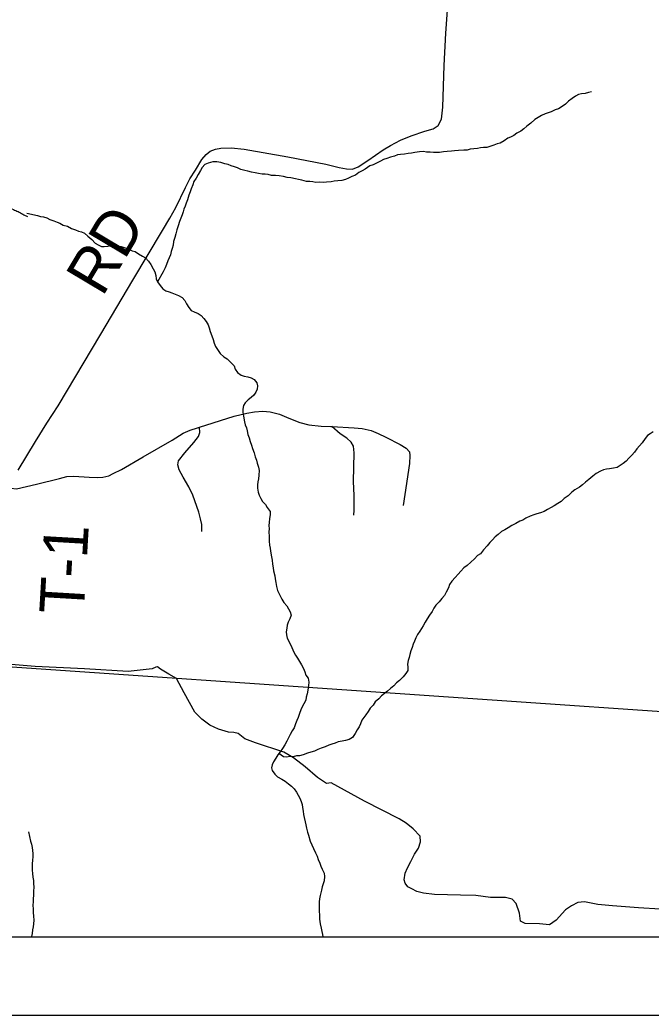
# Model space of a CAD drawing. Extents: x -8.2 to 34, y 0 to 22.
# Drawn here: x 7.291 to 8.096, y 14 to 15.27 of the extents above; entities that cross this region are included whole.
import ezdxf

# ---------------------------------------------------------------- set-up
doc = ezdxf.new("R2010")
doc.units = 0
for name, color, linetype in [('GM_X_Corporation', 7, 'Continuous'), ('GM_X_Minor_River', 7, 'Continuous'), ('GM_X_Township_Road', 7, 'Continuous'), ('GM_X_Township_Road_Text', 7, 'Continuous'), ('SH_Data', 7, 'Continuous')]:
    doc.layers.add(name, color=color, linetype=linetype)

msp = doc.modelspace()

# ---------------------------------------------------------------- linework, layer by layer
at = {"layer": 'GM_X_Corporation'}
for points in [[(4.1481, 14.1), (8.9, 14.1), (8.9, 15.3663), (8.5054, 15.392), (7.8479, 15.4343), (7.082, 15.4841), (6.7558, 15.5053), (6.7389, 15.5064), (6.2987, 15.5287), (5.4088, 15.5882), (4.4836, 15.6492), (4.4152, 15.6505), (4.2922, 15.6569), (4.2674, 15.658), (4.2558, 15.6585), (4.2352, 15.4906), (4.2113, 15.0848), (4.1846, 14.6878), (4.1741, 14.5315), (4.1604, 14.3288)], [(7.2372, 14.1), (8.2568, 14.1), (8.2775, 14.3753), (7.2616, 14.4454)]]:
    msp.add_lwpolyline(points, close=True, dxfattribs=at)
at = {"layer": 'GM_X_Minor_River'}
for points in [[(8.0203, 15.1781), (8.0165, 15.177), (8.0123, 15.1758), (8.0078, 15.1755), (8.004, 15.1747), (7.9998, 15.1724), (7.9956, 15.1694), (7.9911, 15.1659), (7.9873, 15.1621), (7.9831, 15.1595), (7.9782, 15.1564), (7.974, 15.1549), (7.9687, 15.1526), (7.9649, 15.1511), (7.9611, 15.1499), (7.9566, 15.148), (7.9524, 15.1453), (7.9482, 15.1427), (7.9429, 15.1381), (7.938, 15.1343), (7.9338, 15.1309), (7.93, 15.1278), (7.9251, 15.1252), (7.9213, 15.1225), (7.9171, 15.1202), (7.9134, 15.1187), (7.9088, 15.1156), (7.9039, 15.1126), (7.9001, 15.1115), (7.8959, 15.1099), (7.8917, 15.1088), (7.8868, 15.1072), (7.8826, 15.1069), (7.8788, 15.1065), (7.875, 15.1057), (7.8701, 15.1053), (7.8655, 15.1049), (7.8617, 15.1038), (7.8572, 15.1038), (7.8504, 15.103), (7.8454, 15.1026), (7.8416, 15.1022), (7.8363, 15.1018), (7.8314, 15.1014), (7.8264, 15.1006), (7.8223, 15.1006), (7.8185, 15.1006), (7.8143, 15.101), (7.8097, 15.101), (7.8059, 15.1017), (7.8006, 15.1013), (7.7949, 15.1006), (7.7907, 15.0998), (7.7862, 15.0994), (7.7816, 15.0986), (7.7767, 15.0982), (7.7729, 15.0975), (7.7687, 15.0959), (7.7638, 15.0948), (7.7589, 15.0929), (7.7547, 15.0917), (7.7509, 15.0895), (7.7467, 15.0875), (7.7418, 15.0849), (7.7376, 15.0834), (7.7316, 15.0795), (7.7274, 15.0773), (7.7232, 15.075), (7.7191, 15.0719), (7.7145, 15.07), (7.7103, 15.0677), (7.7062, 15.0662), (7.7016, 15.0647), (7.6967, 15.0643), (7.6917, 15.0639), (7.6879, 15.0631), (7.6822, 15.0627), (7.6777, 15.0623), (7.6731, 15.0627), (7.6686, 15.0623), (7.6648, 15.0631), (7.6606, 15.0634), (7.6564, 15.0638), (7.6507, 15.0653), (7.6462, 15.0661), (7.6424, 15.0672), (7.6367, 15.0683), (7.6317, 15.0687), (7.6272, 15.0698), (7.6215, 15.0709), (7.6169, 15.0713), (7.612, 15.0713), (7.6074, 15.0724), (7.6036, 15.0728), (7.5998, 15.0728), (7.5953, 15.0739), (7.5911, 15.0746), (7.5865, 15.0754), (7.5816, 15.0769), (7.5778, 15.0776), (7.5725, 15.0791)], [(7.5725, 15.0791), (7.5683, 15.081), (7.5645, 15.0825), (7.5603, 15.0837), (7.5565, 15.0852), (7.5523, 15.0863), (7.547, 15.0878), (7.5421, 15.0886), (7.5371, 15.0885), (7.531, 15.087), (7.5269, 15.0851), (7.5235, 15.0813), (7.5212, 15.0775), (7.5182, 15.0726), (7.5155, 15.068), (7.5125, 15.0634), (7.5114, 15.0593), (7.5095, 15.0543), (7.508, 15.0505), (7.5065, 15.046), (7.5046, 15.0403), (7.5031, 15.0361), (7.5016, 15.0323), (7.5001, 15.0285), (7.4989, 15.0247), (7.4978, 15.0209), (7.4959, 15.0167), (7.4944, 15.0126), (7.4925, 15.0069), (7.491, 15.0019), (7.4895, 14.997), (7.4884, 14.9921), (7.4869, 14.9871), (7.4861, 14.9822), (7.485, 14.978), (7.4839, 14.9742), (7.4827, 14.9701), (7.4812, 14.9663), (7.4797, 14.9625), (7.4778, 14.9579), (7.4763, 14.9533), (7.4737, 14.9484), (7.4662, 14.9354)], [(7.2994, 15.0231), (7.3129, 15.0201), (7.3171, 15.019), (7.3209, 15.0186), (7.325, 15.0171), (7.3288, 15.0152), (7.3338, 15.0133), (7.338, 15.0118), (7.3418, 15.0103), (7.3459, 15.008), (7.3513, 15.0065), (7.3566, 15.0035), (7.3615, 15.002), (7.3653, 15.0001), (7.3691, 14.9994), (7.3733, 14.9975), (7.3775, 14.9937), (7.3824, 14.9895), (7.3866, 14.985), (7.3904, 14.9827), (7.3946, 14.9805), (7.3984, 14.9805), (7.403, 14.9809), (7.4072, 14.982), (7.4109, 14.982), (7.4155, 14.9816), (7.4201, 14.9805), (7.425, 14.979), (7.4292, 14.9771), (7.4338, 14.9752), (7.4379, 14.9741), (7.4421, 14.9715), (7.4471, 14.9684), (7.4509, 14.9662), (7.4547, 14.962), (7.4577, 14.9575), (7.4608, 14.9522), (7.4631, 14.9484), (7.4642, 14.9438), (7.4646, 14.9393), (7.4661, 14.9355), (7.4696, 14.931), (7.473, 14.9268), (7.4768, 14.9241), (7.481, 14.923), (7.4848, 14.9215), (7.489, 14.92), (7.4931, 14.9181), (7.4977, 14.9155), (7.5011, 14.9117), (7.5034, 14.9075), (7.5061, 14.903), (7.5091, 14.8992), (7.5133, 14.8973), (7.5183, 14.895), (7.5221, 14.8928), (7.5255, 14.889), (7.5285, 14.8848), (7.5308, 14.8807), (7.5324, 14.8769), (7.5335, 14.8723), (7.5358, 14.8666), (7.5373, 14.8621), (7.5385, 14.8575), (7.5404, 14.853), (7.5438, 14.8481), (7.5461, 14.8443), (7.5511, 14.8401), (7.5552, 14.8375), (7.5598, 14.8326), (7.564, 14.8284), (7.5655, 14.8242), (7.5686, 14.8201), (7.5732, 14.8167), (7.577, 14.8152), (7.5815, 14.8144), (7.5861, 14.8129), (7.5899, 14.811), (7.5933, 14.8069), (7.5941, 14.8031), (7.5937, 14.7985), (7.5918, 14.7947), (7.5895, 14.7909), (7.5858, 14.7882), (7.582, 14.7852), (7.5782, 14.7814), (7.5763, 14.7776), (7.5752, 14.7731), (7.5752, 14.7693), (7.5759, 14.7643), (7.5775, 14.7571), (7.5783, 14.7533), (7.5798, 14.7492), (7.5806, 14.7454), (7.5817, 14.7408), (7.5832, 14.7367), (7.5848, 14.7317), (7.5863, 14.7272), (7.5878, 14.723), (7.5897, 14.7173), (7.5909, 14.7124)], [(8.0993, 14.744), (8.0955, 14.7417), (8.0917, 14.7395), (8.0887, 14.7357), (8.0849, 14.7303), (8.0815, 14.7265), (8.0784, 14.7227), (8.0754, 14.7182), (8.072, 14.7144), (8.0682, 14.7106), (8.0648, 14.7068), (8.061, 14.7037), (8.0572, 14.7011), (8.0531, 14.6988), (8.0485, 14.698), (8.0432, 14.6969), (8.0394, 14.6965), (8.0356, 14.6957), (8.0318, 14.6942), (8.0265, 14.6911), (8.022, 14.6877), (8.017, 14.6835), (8.0129, 14.6801), (8.0087, 14.6767), (8.0049, 14.6736), (7.9992, 14.6702), (7.9954, 14.6671), (7.9905, 14.6626), (7.9856, 14.6592), (7.9818, 14.6554)], [(7.5909, 14.7124), (7.5928, 14.7082), (7.5936, 14.7044), (7.5951, 14.6991), (7.5959, 14.695), (7.5955, 14.6889), (7.5951, 14.6844), (7.5944, 14.6806), (7.594, 14.6764), (7.594, 14.6722), (7.5948, 14.6673), (7.596, 14.6635), (7.5982, 14.6593), (7.6002, 14.6555), (7.604, 14.6514), (7.6063, 14.6476), (7.6101, 14.6427), (7.6101, 14.6381), (7.6093, 14.6336), (7.609, 14.6286), (7.6086, 14.6248), (7.609, 14.6203), (7.6086, 14.6165), (7.609, 14.6108), (7.609, 14.6047), (7.6094, 14.5998), (7.6102, 14.5956), (7.6106, 14.5918), (7.6117, 14.5846), (7.6125, 14.5805), (7.6133, 14.5755), (7.614, 14.5706), (7.6144, 14.5668), (7.616, 14.5604), (7.6167, 14.5566), (7.6175, 14.552), (7.6183, 14.5467), (7.6194, 14.5418), (7.6221, 14.5365), (7.6252, 14.5308), (7.6278, 14.5263), (7.6313, 14.5221), (7.6336, 14.5183), (7.6355, 14.5145), (7.637, 14.5104), (7.6351, 14.5058), (7.6332, 14.5013), (7.6317, 14.4975), (7.6313, 14.4937), (7.6306, 14.4891), (7.631, 14.4853), (7.6318, 14.4808), (7.6348, 14.4755), (7.6379, 14.469), (7.6405, 14.463), (7.6424, 14.4592), (7.6451, 14.4554), (7.6474, 14.4512), (7.6501, 14.4467), (7.6527, 14.4421), (7.6543, 14.438), (7.6558, 14.4338), (7.6585, 14.43), (7.6596, 14.4247), (7.6589, 14.4205), (7.6581, 14.4145), (7.6574, 14.4099), (7.6563, 14.4057), (7.6555, 14.4019), (7.6532, 14.397), (7.651, 14.3932), (7.6495, 14.3894), (7.6476, 14.3849), (7.6457, 14.3799), (7.6442, 14.3757), (7.6427, 14.3716), (7.6408, 14.3666), (7.6381, 14.3625), (7.6355, 14.3579), (7.6336, 14.3537), (7.6313, 14.3495), (7.6287, 14.345), (7.626, 14.3401), (7.623, 14.3359), (7.62, 14.3321), (7.6173, 14.3279), (7.6143, 14.3233), (7.6128, 14.3195), (7.6117, 14.3157), (7.6125, 14.3119), (7.6159, 14.3074), (7.6197, 14.304), (7.625, 14.301), (7.6292, 14.2983), (7.6334, 14.2949), (7.6372, 14.2923), (7.641, 14.2885), (7.6437, 14.2843), (7.6459, 14.2806), (7.6479, 14.2768), (7.6498, 14.2726)], [(7.9818, 14.6554), (7.9776, 14.6527), (7.9727, 14.6496), (7.9689, 14.6477), (7.9643, 14.6451), (7.9598, 14.6424), (7.9552, 14.6409), (7.9507, 14.6397), (7.9469, 14.6382), (7.9423, 14.6367), (7.9367, 14.634), (7.9329, 14.6317), (7.9287, 14.6302), (7.9238, 14.6271), (7.9185, 14.6245), (7.9139, 14.6218), (7.9097, 14.6191), (7.9056, 14.6169), (7.9014, 14.6131), (7.8976, 14.6104), (7.8942, 14.6066), (7.8908, 14.6028), (7.887, 14.5986), (7.8825, 14.5937), (7.8787, 14.5887), (7.8749, 14.5864), (7.8711, 14.5823), (7.8662, 14.5781), (7.8616, 14.5735), (7.8575, 14.5705), (7.8537, 14.5663), (7.8503, 14.5625), (7.8465, 14.5583), (7.8419, 14.5537), (7.8393, 14.5496), (7.8378, 14.545), (7.8348, 14.5397), (7.8329, 14.5355), (7.8295, 14.5317), (7.8257, 14.5271), (7.8215, 14.523), (7.8189, 14.5192), (7.817, 14.515), (7.8136, 14.5101), (7.8105, 14.5055), (7.8079, 14.5013), (7.8056, 14.4968), (7.8011, 14.4899), (7.7984, 14.4857), (7.7962, 14.4812), (7.7943, 14.477), (7.7928, 14.4732), (7.7913, 14.469), (7.7898, 14.4649), (7.7886, 14.4603), (7.7875, 14.4561), (7.7864, 14.4523), (7.7856, 14.4478), (7.786, 14.444), (7.7857, 14.4398), (7.7834, 14.436), (7.78, 14.4318), (7.7754, 14.4269), (7.7713, 14.4239), (7.7679, 14.4201), (7.7637, 14.4166), (7.7599, 14.4132), (7.7561, 14.4105), (7.7523, 14.4075), (7.7489, 14.4037), (7.7444, 14.3999), (7.7417, 14.3953), (7.7379, 14.3915), (7.7353, 14.3874), (7.7323, 14.3832), (7.7273, 14.3763), (7.7255, 14.3718), (7.7236, 14.368), (7.7213, 14.3638), (7.7187, 14.3592), (7.7152, 14.3543), (7.7111, 14.3516), (7.7065, 14.3505), (7.702, 14.3497), (7.697, 14.3486), (7.6932, 14.347), (7.6887, 14.3455), (7.6849, 14.3444), (7.6803, 14.3421), (7.6754, 14.3406), (7.6709, 14.339), (7.6667, 14.3367), (7.6621, 14.3356), (7.6576, 14.3341), (7.6523, 14.3322), (7.6477, 14.331), (7.6439, 14.3306), (7.6394, 14.3295), (7.6356, 14.3298), (7.631, 14.3291), (7.6272, 14.3294)], [(7.6272, 14.3294), (7.6212, 14.3336)], [(7.6498, 14.2726), (7.6509, 14.2688), (7.6513, 14.265), (7.6521, 14.2601), (7.6528, 14.2559), (7.6536, 14.2521), (7.6548, 14.2468), (7.6555, 14.2427), (7.6567, 14.2385), (7.6578, 14.2336), (7.659, 14.2294), (7.6613, 14.2218), (7.6632, 14.2173), (7.6655, 14.2127), (7.6682, 14.207), (7.6701, 14.2029), (7.6716, 14.1987), (7.6735, 14.1938), (7.675, 14.19), (7.6766, 14.1862), (7.6789, 14.1809), (7.6796, 14.1767), (7.6789, 14.1714), (7.6778, 14.1676), (7.6766, 14.1638), (7.6755, 14.1593), (7.674, 14.1524), (7.6733, 14.1483), (7.6729, 14.1445), (7.6729, 14.1403), (7.6729, 14.1361), (7.6729, 14.1323), (7.6733, 14.1278), (7.6733, 14.1225), (7.6741, 14.1164), (7.6753, 14.1111), (7.676, 14.1065), (7.6768, 14.1028), (7.6774, 14.1)], [(7.3015, 14.2338), (7.304, 14.222), (7.3055, 14.2179), (7.3063, 14.2137), (7.3067, 14.2099), (7.307, 14.2061), (7.3071, 14.202), (7.3067, 14.1978), (7.3063, 14.1929), (7.3063, 14.1887), (7.3063, 14.1849), (7.3067, 14.1807), (7.3071, 14.1758), (7.3079, 14.1716), (7.3079, 14.1678), (7.3083, 14.1633), (7.3079, 14.1583), (7.3079, 14.153), (7.3076, 14.1485), (7.3076, 14.1447), (7.3072, 14.1401), (7.3076, 14.1352), (7.3076, 14.131), (7.308, 14.1261), (7.3084, 14.1212), (7.308, 14.1166), (7.3077, 14.1128), (7.3069, 14.1087), (7.3062, 14.1041), (7.3054, 14.1003), (7.3054, 14.1)]]:
    msp.add_lwpolyline(points, dxfattribs=at)
msp.add_spline([(7.0807, 15.1515), (7.0868, 15.1524), (7.0944, 15.151), (7.1023, 15.1496), (7.1087, 15.1471), (7.1158, 15.1442), (7.1221, 15.1398), (7.1303, 15.1361), (7.137, 15.1325), (7.1452, 15.1269), (7.1522, 15.1217), (7.1626, 15.1138), (7.1715, 15.1074), (7.1801, 15.1022), (7.1882, 15.097), (7.1953, 15.0926), (7.2016, 15.0886), (7.2094, 15.0826), (7.2154, 15.079), (7.2213, 15.075), (7.2287, 15.0695), (7.2354, 15.0639), (7.2423, 15.0572), (7.249, 15.0521), (7.2546, 15.0477), (7.2616, 15.0414), (7.2679, 15.0366), (7.2746, 15.0326), (7.2824, 15.0278), (7.2884, 15.0253), (7.2943, 15.0221), (7.3003, 15.0188)], degree=3, dxfattribs=at)
at = {"layer": 'GM_X_Township_Road'}
for points in [[(7.2885, 14.6953), (7.3105, 14.7317), (7.3252, 14.7554), (7.3395, 14.7774), (7.3941, 14.869), (7.435, 14.9377), (7.4728, 15.0009), (7.4822, 15.0168), (7.4896, 15.0305), (7.5019, 15.0561), (7.5076, 15.0669), (7.5147, 15.0779), (7.5231, 15.0916), (7.5284, 15.0982), (7.5337, 15.1022), (7.5405, 15.1047), (7.5472, 15.1063), (7.5605, 15.1065), (7.5769, 15.1047), (7.6329, 15.0949), (7.6811, 15.0857), (7.6981, 15.0814), (7.7075, 15.0796), (7.7153, 15.0794), (7.7226, 15.0822), (7.7347, 15.0902), (7.7543, 15.1039), (7.7639, 15.1094), (7.7766, 15.1164), (7.7903, 15.1219), (7.8077, 15.1278), (7.8181, 15.1309), (7.8248, 15.135), (7.8289, 15.1433), (7.8307, 15.1583), (7.8324, 15.2116), (7.8346, 15.2527), (7.8439, 15.3826)], [(7.5172, 14.7494), (7.52, 14.7502), (7.5641, 14.7641), (7.5803, 14.768), (7.59, 14.7699), (7.6006, 14.7706), (7.6101, 14.7698), (7.6221, 14.7668), (7.634, 14.7617), (7.6482, 14.756), (7.6597, 14.7532), (7.6751, 14.7514), (7.6878, 14.7512)], [(7.2792, 14.6724), (7.2862, 14.6714), (7.3117, 14.6775), (7.3412, 14.6846), (7.3507, 14.687), (7.3594, 14.6876), (7.3791, 14.6862), (7.3894, 14.686), (7.3967, 14.6864), (7.404, 14.6882), (7.4099, 14.691), (7.4202, 14.6961), (7.4479, 14.7122), (7.4852, 14.7337), (7.4989, 14.7425), (7.5078, 14.7465), (7.5172, 14.7494)], [(7.5228, 14.617), (7.5228, 14.6261), (7.5214, 14.6331), (7.519, 14.6419), (7.5113, 14.6635), (7.5062, 14.6742), (7.4991, 14.6864), (7.4939, 14.6957), (7.4923, 14.7022), (7.4931, 14.7072), (7.5011, 14.7174), (7.5129, 14.7307), (7.5188, 14.7384), (7.5202, 14.7435), (7.52, 14.7502)], [(7.6878, 14.7512), (7.6888, 14.7512), (7.7174, 14.7493), (7.7275, 14.7484), (7.7391, 14.7457), (7.7482, 14.7421), (7.7579, 14.7374), (7.7761, 14.7279), (7.7838, 14.7234), (7.7881, 14.7188), (7.7885, 14.7141), (7.788, 14.704), (7.7822, 14.6643), (7.7799, 14.6502)], [(7.7168, 14.6378), (7.7174, 14.6443), (7.7174, 14.6502), (7.7174, 14.6629), (7.7166, 14.6809), (7.7172, 14.7176), (7.7164, 14.7259), (7.7135, 14.7311), (7.7079, 14.736), (7.6996, 14.7415), (7.6888, 14.7512)], [(7.5005, 14.411), (7.4904, 14.4293), (7.4808, 14.4349), (7.4701, 14.4415), (7.4665, 14.4442), (7.4643, 14.4441), (7.4593, 14.4416), (7.4287, 14.4384), (7.3731, 14.4416), (7.3103, 14.4448), (7.2692, 14.4482)], [(7.9357, 14.117), (7.9298, 14.12), (7.9284, 14.1299), (7.9244, 14.1425), (7.9192, 14.1478), (7.9107, 14.1499), (7.8913, 14.1502), (7.8729, 14.1524), (7.8533, 14.1529), (7.8201, 14.1538), (7.8059, 14.1557), (7.7972, 14.1575), (7.7908, 14.1609), (7.7859, 14.1637), (7.7826, 14.1683), (7.7811, 14.1727), (7.7826, 14.1812), (7.7853, 14.1879), (7.7899, 14.196), (7.7946, 14.2052), (7.7995, 14.2132), (7.8022, 14.2211), (7.8017, 14.2285), (7.7927, 14.2377), (7.7838, 14.2451), (7.7748, 14.2506), (7.7306, 14.2731), (7.6881, 14.2962), (7.6819, 14.2956), (7.6704, 14.3033), (7.6547, 14.3169), (7.6401, 14.3284), (7.6276, 14.3355), (7.5915, 14.3472), (7.5777, 14.3527), (7.5695, 14.3592), (7.5639, 14.3607), (7.5568, 14.3611), (7.5443, 14.3648), (7.5332, 14.3698), (7.523, 14.3776), (7.514, 14.3867), (7.5005, 14.411)], [(8.1715, 14.1228), (8.1404, 14.1302), (8.1235, 14.1336), (8.1079, 14.135), (8.0806, 14.1369), (8.0472, 14.1394), (8.0286, 14.1412), (8.0116, 14.1446), (8.0028, 14.1437), (7.995, 14.1394), (7.9873, 14.1345), (7.9753, 14.121), (7.9667, 14.1151), (7.9539, 14.1164), (7.9357, 14.117)]]:
    msp.add_lwpolyline(points, dxfattribs=at)
at = {"layer": 'SH_Data'}
for p, q in [((4.1481, 14.1), (8.9, 14.1)), ((2, 14), (9, 14))]:
    msp.add_line(p, q, dxfattribs=at)

# ---------------------------------------------------------------- texts
at = {"layer": 'GM_X_Township_Road_Text'}
for s, rotation, p in [('RD', 59.2073, (7.3959, 14.9153)), ('T-1', 86.6532, (7.372, 14.5105))]:
    msp.add_text(s, height=0.05682, rotation=rotation, dxfattribs=at).set_placement(p)

doc.saveas('drawing.dxf')
